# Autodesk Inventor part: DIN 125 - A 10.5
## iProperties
Comments: To add or edit properties for Autodesk Inventor files, use iProperties.
Created: 2003-09
Part Number: DIN 125 - A 10.5
Vendor: Autodesk Inc.
Document SubType Name: Modeling
Designer: lamberj
Material: Default
Description: Washer
Standard: DIN 125
Manufacturer: Standard
Standards Organization: Custom
Alert: To add or edit properties for Autodesk Inventor files, use iProperties.
Control State: 0
Master: False
Checked Out: False
Shininess: 64.0
Length Units: 11269
Angle Units: 11279
Time Units: 11290
Mass Units: 11283
Length Display Precision: 3
Angle Display Precision: 2
Compacted: True
Classification: un/spsc 31161807
Density: 0.0
Volumn: 0.0
Area: 0.0
PropertySet Name: Model Information
Author: lamberj
Revision Number: 5
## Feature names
1. Body [Extrusion]
